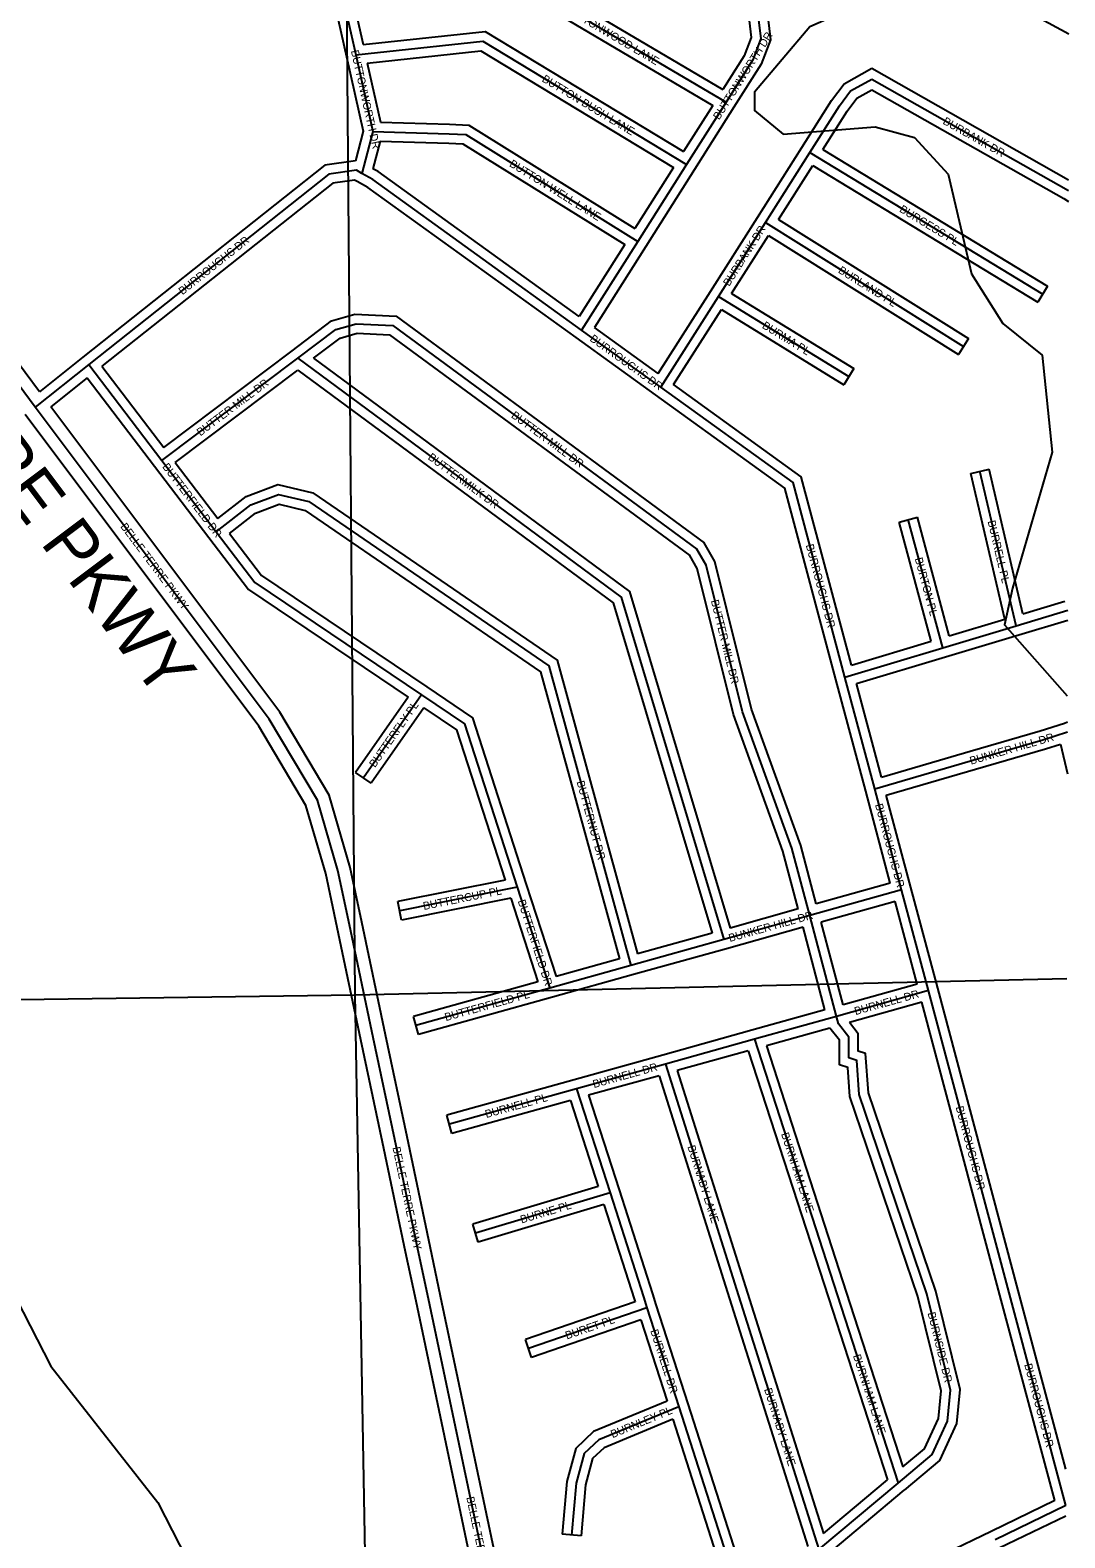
# Model space of a CAD drawing. Extents: x 457167 to 656239, y 1787309 to 1969297.
# Drawn here: x 573475 to 576766, y 1906785 to 1911582 of the extents above; entities that cross this region are included whole.
import ezdxf

# ---------------------------------------------------------------- set-up
doc = ezdxf.new("R2010")
doc.units = 0
for name, color, linetype in [('Level 1', 7, 'Continuous'), ('Level 22', 7, 'Continuous'), ('Level 23', 7, 'Continuous'), ('Level 28', 7, 'Continuous'), ('Level 31', 7, 'Continuous'), ('Level 32', 7, 'Continuous'), ('Level 34', 7, 'Continuous'), ('Level 7', 7, 'Continuous')]:
    doc.layers.add(name, color=color, linetype=linetype)

msp = doc.modelspace()

# ---------------------------------------------------------------- linework, layer by layer
at = {"layer": 'Level 1'}
for p, q in [((574508.155, 1908512.577), (574465.56, 1913625.261)), ((574508.155, 1908512.577), (576773.088, 1908564.556)), ((569209.114, 1908436.293), (574508.155, 1908512.577)), ((574605.324, 1903226.441), (574508.155, 1908512.577))]:
    msp.add_line(p, q, dxfattribs=at)
at = {"layer": 'Level 22'}
for p, q in [((573490.678, 1910382.465), (572685.119, 1911456.291)), ((574566.005, 1908377.134), (574490.505, 1908735.125)), ((574634.585, 1908052.25), (574566.005, 1908377.134)), ((574708.201, 1907703.355), (574634.585, 1908052.25)), ((574741.549, 1907545.461), (574708.201, 1907703.355)), ((575070.95, 1905983.62), (574741.549, 1907545.461))]:
    msp.add_line(p, q, dxfattribs=at)
msp.add_lwpolyline([(574490.505, 1908735.125), (574454.014, 1908907.936), (574388.708, 1909131.357), (574235.434, 1909389.518), (573490.678, 1910382.465)], dxfattribs=at)
at = {"layer": 'Level 23'}
for p, q in [((573504.03, 1910431.324), (572735.449, 1911455.859)), ((574526.865, 1908368.879), (574451.365, 1908726.871)), ((574605.144, 1908385.388), (574529.645, 1908743.379)), ((574595.448, 1908043.987), (574526.866, 1908368.871)), ((574673.725, 1908060.511), (574605.143, 1908385.396)), ((574669.062, 1907695.096), (574595.447, 1908043.991)), ((574747.341, 1907711.613), (574673.725, 1908060.508)), ((574702.411, 1907537.194), (574669.064, 1907695.088)), ((574780.687, 1907553.726), (574747.34, 1907711.621)), ((575104.96, 1906016.193), (574780.689, 1907553.715)), ((575031.81, 1905975.365), (574702.41, 1907537.206))]:
    msp.add_line(p, q, dxfattribs=at)
for points in [[(574529.642, 1908743.39), (574492.835, 1908917.694), (574425.685, 1909147.431), (574268.728, 1909411.795), (573540.047, 1910383.308)], [(574451.367, 1908726.861), (574415.191, 1908898.179), (574351.732, 1909115.283), (574202.139, 1909367.242), (573458.679, 1910358.462)]]:
    msp.add_lwpolyline(points, dxfattribs=at)
at = {"layer": 'Level 31'}
for p, q in [((574461.171, 1911722.884), (574510.587, 1911503.135)), ((574510.587, 1911503.135), (574564.721, 1911259.737)), ((575688.499, 1911352.555), (575563.155, 1911154.278)), ((574564.721, 1911259.737), (574530.099, 1911125.993)), ((575813.853, 1910969.73), (575955.14, 1911192.337)), ((575955.14, 1911192.337), (576696.021, 1910741.641)), ((575563.155, 1911154.278), (575408.15, 1910909.52)), ((575664.272, 1910734.414), (575813.853, 1910969.73)), ((575813.853, 1910969.73), (576444.564, 1910575.27)), ((575408.15, 1910909.52), (575229.223, 1910627.722)), ((575481.2, 1910446.079), (575664.272, 1910734.414)), ((575664.272, 1910734.414), (576079.148, 1910479.328)), ((575481.2, 1910446.079), (575229.223, 1910627.722)), ((573893.972, 1910212.473), (574326.015, 1910537.705)), ((573661.347, 1910517.723), (573490.678, 1910382.465)), ((573661.347, 1910517.723), (573893.972, 1910212.473)), ((573893.972, 1910212.473), (574066.7, 1909985.903)), ((576611.118, 1909686.896), (576496.156, 1910178.424)), ((576377.978, 1909616.85), (576268.241, 1910024.366)), ((576611.118, 1909686.896), (576775.555, 1909736.362)), ((576377.978, 1909616.85), (576611.118, 1909686.896)), ((576066.912, 1909523.336), (576377.978, 1909616.85)), ((576161.82, 1909167.853), (576066.912, 1909523.336)), ((574719.387, 1909467.363), (574534.764, 1909202.673)), ((576474.155, 1909259.181), (576696.162, 1909324.161)), ((576696.162, 1909324.161), (576774.725, 1909348.72)), ((576161.82, 1909167.853), (576474.155, 1909259.181)), ((576247.268, 1908846.571), (576161.82, 1909167.853)), ((575024.462, 1908854.682), (574650.489, 1908779.501)), ((575024.462, 1908854.682), (575128.02, 1908533.722)), ((576247.268, 1908846.571), (575954.655, 1908764.656)), ((576333.036, 1908525.654), (576247.268, 1908846.571)), ((575954.655, 1908764.656), (575681.761, 1908688.155)), ((576039.785, 1908443.739), (575954.655, 1908764.656)), ((575681.761, 1908688.155), (575385.966, 1908605.525)), ((575385.966, 1908605.525), (575128.02, 1908533.722)), ((575128.02, 1908533.722), (574701.817, 1908415.018)), ((576333.036, 1908525.654), (576039.785, 1908443.739)), ((576589.081, 1907564.359), (576333.036, 1908525.654)), ((576039.785, 1908443.739), (575778.976, 1908370.848)), ((575778.976, 1908370.848), (575495.584, 1908291.826)), ((575778.976, 1908370.848), (576042.639, 1907557.535)), ((575495.584, 1908291.826), (575213.144, 1908213.167)), ((575495.584, 1908291.826), (575728.572, 1907554.579)), ((575213.144, 1908213.167), (574808.567, 1908100.596)), ((575213.144, 1908213.167), (575319.545, 1907882.384)), ((575319.545, 1907882.384), (574891.725, 1907753.861)), ((575319.545, 1907882.384), (575425.63, 1907551.601)), ((575425.63, 1907551.601), (575436.998, 1907516.666)), ((575728.572, 1907554.579), (575983.352, 1906747.104)), ((576042.639, 1907557.535), (576236.524, 1906958.925)), ((576403.092, 1907254.207), (576327.462, 1907560.557)), ((576769.456, 1906887.233), (576589.081, 1907564.359)), ((575436.998, 1907516.666), (575060.35, 1907386.941)), ((575436.998, 1907516.666), (575538.351, 1907201.895)), ((575538.351, 1907201.895), (575747.69, 1906549.792)), ((575983.352, 1906747.104), (576236.524, 1906958.925)), ((576769.456, 1906887.233), (576544.798, 1906778.259))]:
    msp.add_line(p, q, dxfattribs=at)
for points in [[(574705.365, 1911764.892), (574925.71, 1911802.956), (575688.499, 1911352.555)], [(575790.176, 1911630.885), (575799.546, 1911554.863), (575773.336, 1911486.919), (575688.499, 1911352.555)], [(574510.587, 1911503.135), (574915.295, 1911546.973), (575563.155, 1911154.278)], [(575955.14, 1911192.337), (576049.225, 1911341.228), (576084.29, 1911388.426), (576152.072, 1911426.098)], [(576152.072, 1911426.098), (576778.415, 1911071.653), (576778.453, 1911071.63)], [(574564.721, 1911259.737), (574807.855, 1911252.294), (574860.611, 1911249.633), (575408.15, 1910909.52)], [(574530.099, 1911125.993), (574512.639, 1911135.85), (574424.887, 1911123.679), (573661.347, 1910517.723)], [(575229.223, 1910627.722), (574565.337, 1911106.642), (574530.099, 1911125.993)], [(574326.015, 1910537.705), (574447.319, 1910629.438), (574511.564, 1910647.479), (574628.838, 1910642.13), (575595.777, 1909930.547)], [(574326.015, 1910537.705), (575355.464, 1909777.976), (575681.761, 1908688.155)], [(576066.912, 1909523.336), (575901.695, 1910142.979), (575481.2, 1910446.079)], [(574066.7, 1909985.903), (574176.867, 1910071.843), (574264.666, 1910104.376), (574361.562, 1910081.616), (575124.857, 1909558.84), (575385.966, 1908605.525)], [(574066.7, 1909985.903), (574189.67, 1909824.537), (574719.387, 1909467.363)], [(575954.655, 1908764.656), (575897.585, 1908978.966), (575740.55, 1909412.768), (575624.91, 1909879.937), (575595.777, 1909930.547)], [(574719.387, 1909467.363), (574856.182, 1909375.061), (575024.462, 1908854.682)], [(576327.462, 1907560.557), (576112.358, 1908194.851), (576104.327, 1908303.234), (576079.234, 1908311.652), (576079.377, 1908378.198), (576046.092, 1908420.089), (576039.785, 1908443.739)], [(576236.524, 1906958.925), (576344.163, 1907049.603), (576393.664, 1907156.044), (576403.092, 1907254.207)], [(575538.351, 1907201.895), (575283.82, 1907096.992), (575237.313, 1907052.73), (575211.358, 1906958.239), (575197.33, 1906793.54)]]:
    msp.add_lwpolyline(points, dxfattribs=at)
at = {"layer": 'Level 32'}
for p, q in [((574431.902, 1911716.302), (574481.319, 1911496.552)), ((574497.366, 1911698.668), (574533.981, 1911535.844)), ((576649.511, 1911639.646), (576779.519, 1911570.011)), ((574481.303, 1911496.621), (574533.87, 1911260.268)), ((574547.153, 1911476.918), (574588.945, 1911289.011)), ((576152.205, 1911460.493), (576778.526, 1911106.061)), ((575646.616, 1911342.445), (575553.53, 1911195.194)), ((575713.858, 1911336.524), (575588.515, 1911138.247)), ((574533.87, 1911260.269), (574509.385, 1911165.686)), ((574587.76, 1911229.016), (574564.99, 1911141.059)), ((575788.524, 1910985.806), (575929.811, 1911208.413)), ((575996.804, 1911202.108), (576711.614, 1910767.272)), ((575521.441, 1911144.481), (575398.717, 1910950.696)), ((575855.367, 1910979.151), (575964.696, 1911151.408)), ((575964.696, 1911151.407), (576680.43, 1910716.01)), ((575588.501, 1911138.226), (575433.495, 1910893.468)), ((575638.954, 1910750.507), (575788.535, 1910985.823)), ((575855.367, 1910979.151), (576460.472, 1910600.705)), ((575705.928, 1910744.02), (575823.196, 1910928.501)), ((575823.196, 1910928.501), (576428.656, 1910549.834)), ((575366.582, 1910900.022), (575220.96, 1910670.676)), ((575433.477, 1910893.438), (575269.712, 1910635.518)), ((576711.614, 1910767.272), (576680.43, 1910716.01)), ((575472.93, 1910489.022), (575638.945, 1910750.494)), ((575705.928, 1910744.019), (576094.861, 1910504.884)), ((575521.689, 1910453.876), (575673.75, 1910693.369)), ((575673.75, 1910693.369), (576063.435, 1910453.771)), ((575472.93, 1910489.022), (575269.712, 1910635.518)), ((575463.656, 1910421.742), (575211.68, 1910603.386)), ((576460.472, 1910600.705), (576428.656, 1910549.834)), ((573642.714, 1910541.236), (573504.03, 1910431.325)), ((573899.757, 1910254.376), (574307.973, 1910561.672)), ((573656.02, 1910475.219), (573540.046, 1910383.308)), ((573656.02, 1910475.22), (573870.11, 1910194.288)), ((573703.04, 1910512.51), (573899.757, 1910254.377)), ((573936.13, 1910206.656), (574326.194, 1910500.287)), ((576094.861, 1910504.884), (576063.435, 1910453.771)), ((573870.114, 1910194.284), (574042.842, 1909967.714)), ((573936.13, 1910206.656), (574072.167, 1910028.216)), ((576466.945, 1910171.591), (576525.37, 1910185.256)), ((576633.059, 1909724.823), (576525.37, 1910185.256)), ((576575.485, 1909707.514), (576466.945, 1910171.591)), ((576239.274, 1910016.565), (576297.21, 1910032.167)), ((576341.433, 1909637.189), (576239.274, 1910016.565)), ((576398.918, 1909654.466), (576297.21, 1910032.167)), ((576633.058, 1909724.823), (576766.468, 1909764.956)), ((576398.918, 1909654.466), (576575.485, 1909707.515)), ((576619.761, 1909658.166), (576775.528, 1909705.024)), ((576386.611, 1909588.117), (576619.751, 1909658.163)), ((576087.925, 1909560.98), (576341.432, 1909637.19)), ((576103.4, 1909502.976), (576386.615, 1909588.118)), ((576132.835, 1909160.114), (576037.927, 1909515.598)), ((576182.882, 1909205.267), (576103.4, 1909502.978)), ((574677.345, 1909459.527), (574510.158, 1909219.836)), ((574727.095, 1909425.971), (574559.37, 1909185.51)), ((576687.473, 1909352.876), (576764.875, 1909377.072)), ((576764.875, 1909377.072), (576774.835, 1909380.887)), ((576465.729, 1909287.974), (576687.472, 1909352.876)), ((576182.882, 1909205.268), (576465.736, 1909287.976)), ((576482.584, 1909230.388), (576704.853, 1909295.445)), ((576704.852, 1909295.445), (576752.742, 1909310.415)), ((576752.743, 1909310.415), (576774.482, 1909215.836)), ((576198.338, 1909147.273), (576482.576, 1909230.386)), ((574559.37, 1909185.51), (574510.158, 1909219.836)), ((576210.665, 1908867.477), (576132.828, 1909160.141)), ((576276.26, 1908854.281), (576198.338, 1909147.273)), ((574985.566, 1908877.462), (574644.577, 1908808.913)), ((575053.013, 1908863.894), (575147.726, 1908570.348)), ((576210.664, 1908867.478), (575975.828, 1908801.736)), ((576362.02, 1908533.399), (576276.251, 1908854.316)), ((574656.402, 1908750.089), (574644.577, 1908808.913)), ((575004.131, 1908819.994), (574656.402, 1908750.089)), ((575004.132, 1908819.994), (575089.877, 1908554.241)), ((576226.124, 1908809.496), (575991.242, 1908743.743)), ((576296.395, 1908546.566), (576226.124, 1908809.496)), ((575918.046, 1908785.55), (575702.048, 1908724.998)), ((575644.256, 1908708.826), (575406.936, 1908642.531)), ((575933.459, 1908727.556), (575689.86, 1908659.268)), ((576003.198, 1908464.662), (575933.46, 1908727.556)), ((576060.99, 1908480.811), (575991.241, 1908743.744)), ((575689.834, 1908659.261), (575394.039, 1908576.63)), ((575349.14, 1908626.413), (575147.726, 1908570.349)), ((575089.876, 1908554.241), (574693.769, 1908443.919)), ((575394.012, 1908576.622), (575136.065, 1908504.821)), ((576296.395, 1908546.566), (576060.99, 1908480.81)), ((576618.071, 1907572.081), (576362.026, 1908533.375)), ((575136.07, 1908504.821), (574709.867, 1908386.117)), ((576003.198, 1908464.662), (575770.902, 1908399.741)), ((576311.862, 1908488.589), (576081.18, 1908424.152)), ((576560.091, 1907556.636), (576311.862, 1908488.588)), ((574709.867, 1908386.117), (574693.769, 1908443.919)), ((575770.92, 1908399.746), (575487.526, 1908320.724)), ((576018.621, 1908406.673), (575817.154, 1908350.366)), ((575487.535, 1908320.726), (575205.096, 1908242.067)), ((575759.313, 1908334.218), (575533.545, 1908271.265)), ((575759.314, 1908334.218), (576014.101, 1907548.283)), ((575817.154, 1908350.366), (576071.178, 1907566.786)), ((575533.545, 1908271.265), (575757.178, 1907563.619)), ((575205.103, 1908242.069), (574800.525, 1908129.499)), ((575475.712, 1908255.148), (575251.262, 1908192.64)), ((575475.712, 1908255.148), (575699.966, 1907545.539)), ((575193.414, 1908176.536), (574816.609, 1908071.693)), ((575193.414, 1908176.535), (575281.62, 1907902.315)), ((575251.262, 1908192.64), (575348.105, 1907891.57)), ((574816.609, 1908071.693), (574800.525, 1908129.499)), ((575281.62, 1907902.315), (574883.094, 1907782.593)), ((575348.114, 1907891.545), (575454.159, 1907560.883)), ((575299.973, 1907845.177), (574900.357, 1907725.13)), ((575299.972, 1907845.177), (575397.063, 1907542.439)), ((574900.357, 1907725.13), (574883.094, 1907782.593)), ((575454.159, 1907560.883), (575465.526, 1907525.949)), ((575699.962, 1907545.551), (575948.703, 1906757.219)), ((575757.182, 1907563.606), (575998.476, 1906798.873)), ((576014.099, 1907548.291), (576201.745, 1906968.941)), ((576071.18, 1907566.779), (576251.318, 1907010.614)), ((576372.741, 1907251.982), (576298.642, 1907552.128)), ((576433.445, 1907256.431), (576356.283, 1907568.985)), ((576734.097, 1906903.424), (576560.091, 1907556.636)), ((576769.747, 1907002.723), (576618.071, 1907572.081)), ((575399.345, 1907535.427), (575050.58, 1907415.306)), ((575397.102, 1907542.318), (575399.345, 1907535.427)), ((575465.555, 1907525.861), (575566.909, 1907211.09)), ((575417.825, 1907478.331), (575070.12, 1907358.576)), ((575417.825, 1907478.331), (575501.303, 1907219.073)), ((575070.12, 1907358.576), (575050.58, 1907415.306)), ((575566.917, 1907211.065), (575762.625, 1906601.422)), ((575519.725, 1907161.768), (575719.126, 1906540.621)), ((575998.476, 1906798.873), (576201.745, 1906968.941)), ((576002.604, 1906724.095), (576255.775, 1906935.916)), ((576734.097, 1906903.424), (576531.705, 1906805.251)), ((576769.428, 1906853.875), (576557.892, 1906751.266)), ((575227.222, 1906790.994), (575167.438, 1906796.086))]:
    msp.add_line(p, q, dxfattribs=at)
for points in [[(574728.836, 1911799.391), (574931.469, 1911834.396), (575678.679, 1911393.193)], [(574710.47, 1911735.329), (574919.951, 1911771.516), (575646.616, 1911342.445)], [(575818.104, 1911649.545), (575830.241, 1911551.076), (575800.27, 1911473.383), (575713.866, 1911336.538)], [(574533.982, 1911535.844), (574922.161, 1911577.893), (575553.53, 1911195.194)], [(575762.25, 1911612.223), (575768.851, 1911558.651), (575746.402, 1911500.455), (575678.679, 1911393.193)], [(574547.153, 1911476.918), (574908.43, 1911516.053), (575521.44, 1911144.481)], [(575929.779, 1911208.363), (576024.47, 1911358.211), (576064.065, 1911411.507), (576152.205, 1911460.494)], [(575996.803, 1911202.107), (576073.982, 1911324.246), (576104.515, 1911365.343), (576151.94, 1911391.701)], [(576151.94, 1911391.701), (576763.143, 1911045.825), (576778.377, 1911036.421)], [(574588.945, 1911289.011), (574809.07, 1911282.271), (574869.86, 1911279.206), (575398.716, 1910950.696)], [(574587.759, 1911229.016), (574806.64, 1911222.316), (574851.362, 1911220.061), (575366.582, 1910900.022)], [(574509.385, 1911165.686), (574412.654, 1911152.271), (573642.697, 1910541.223)], [(574515.35, 1911099.867), (574506.719, 1911104.741), (574437.121, 1911095.088), (573703.04, 1910512.51)], [(575211.671, 1910603.391), (574549.28, 1911081.233), (574515.35, 1911099.867)], [(575220.96, 1910670.676), (574581.394, 1911132.051), (574564.99, 1911141.059)], [(574307.92, 1910561.633), (574433.747, 1910656.789), (574508.105, 1910677.669), (574639.293, 1910671.685), (575618.635, 1909950.975)], [(574376.141, 1910537.997), (574460.89, 1910602.088), (574515.024, 1910617.289), (574618.383, 1910612.575), (575572.921, 1909910.118)], [(574376.142, 1910537.997), (575381.332, 1909796.171), (575702.047, 1908724.998)], [(574326.193, 1910500.287), (575329.595, 1909759.781), (575644.256, 1908708.826)], [(576087.925, 1909560.98), (575927.925, 1910161.055), (575521.688, 1910453.876)], [(576037.924, 1909515.608), (575875.466, 1910124.903), (575463.657, 1910421.741)], [(574072.167, 1910028.216), (574162.082, 1910098.359), (574262.722, 1910135.651), (574373.884, 1910109.539), (575150.885, 1909577.376), (575406.937, 1908642.531)], [(574108.542, 1909980.493), (574191.653, 1910045.328), (574266.61, 1910073.103), (574349.24, 1910053.694), (575098.829, 1909540.304), (575349.14, 1908626.413)], [(574042.838, 1909967.719), (574168.803, 1909802.424), (574677.345, 1909459.527)], [(574108.541, 1909980.493), (574210.538, 1909846.651), (574736.159, 1909492.237)], [(575975.828, 1908801.736), (575926.24, 1908987.949), (575769.293, 1909421.502), (575653.016, 1909891.245), (575618.635, 1909950.975)], [(575918.046, 1908785.55), (575868.932, 1908969.983), (575711.805, 1909404.035), (575596.802, 1909868.63), (575572.921, 1909910.118)], [(574736.167, 1909492.232), (574881.542, 1909394.141), (575053.007, 1908863.913)], [(574727.095, 1909425.971), (574830.821, 1909355.981), (574985.566, 1908877.463)], [(576356.284, 1907568.985), (576141.994, 1908200.872), (576132.772, 1908325.335), (576109.28, 1908333.216), (576109.4, 1908388.636), (576081.18, 1908424.152)], [(576298.641, 1907552.128), (576082.721, 1908188.828), (576075.882, 1908281.133), (576049.187, 1908290.089), (576049.355, 1908367.759), (576018.715, 1908406.321), (576018.621, 1908406.672)], [(575501.303, 1907219.074), (575267.201, 1907122.592), (575210.593, 1907068.715), (575181.7, 1906963.53), (575167.438, 1906796.086)], [(576251.318, 1907010.614), (576319.759, 1907068.271), (576364.292, 1907164.031), (576372.74, 1907251.983)], [(576255.853, 1906935.981), (576368.567, 1907030.935), (576423.035, 1907148.056), (576433.446, 1907256.431)], [(575519.725, 1907161.768), (575300.44, 1907071.393), (575264.034, 1907036.745), (575241.017, 1906952.949), (575227.222, 1906790.994)], [(576531.745, 1906805.271), (576095.686, 1906594.556), (575995.722, 1906400.816)]]:
    msp.add_lwpolyline(points, dxfattribs=at)
at = {"layer": 'Level 7'}
for points in [[(576780.451, 1912005.73), (576640.126, 1911973.185), (576439.505, 1911807.118), (575955.308, 1911591.906), (575779.587, 1911384.05), (575779.398, 1911325.698), (575870.831, 1911250.377), (576162.706, 1911274.472), (576287.65, 1911240.703), (576395.633, 1911123.661), (576469.639, 1910806.625), (576569.153, 1910647.932), (576693.906, 1910547.471), (576726.241, 1910238.934), (576599.825, 1909805.832), (576574.415, 1909689.219), (576773.772, 1909463.486)], [(573341.919, 1907715.53), (573540.748, 1907331.403), (573881.14, 1906896.837), (574295.369, 1906086.863), (574336.591, 1905945.021), (574502.21, 1905594.334), (574510.32, 1905527.642), (574535.261, 1905510.872), (574535.132, 1905460.851), (574576.643, 1905410.701), (574782.995, 1904776.488), (574797.615, 1904126.182), (574746.448, 1903776.223)]]:
    msp.add_lwpolyline(points, dxfattribs=at)

# ---------------------------------------------------------------- texts
at = {"layer": 'Level 28'}
msp.add_text('BELLE TERRE PKWY', height=160, rotation=306.875711, dxfattribs=at).set_placement((572598.469, 1911158.419))
at = {"layer": 'Level 34'}
for s, height, rotation, p in [('BUTTONWOOD LANE', 25, 329.438986, (575172.196, 1911642.899)), ('BUTTONWORTH DR', 25, 57.730783, (575666.574, 1911294.42)), ('BUTTONWORTH DR', 24.99916, 282.538136, (574494.994, 1911515.686)), ('BUTTON BUSH LANE', 25, 328.777547, (575100.634, 1911420.016)), ('BURBANK DR', 25, 330.494053, (576376.031, 1911284.999)), ('BUTTON WELL LANE', 25, 328.152219, (574996.955, 1911150.227)), ('BURGESS PL', 25, 328.686256, (576237.955, 1911005.664)), ('BURBANK DR', 25, 57.556728, (575698.415, 1910764.828)), ('BURROUGHS DR', 25, 38.435144, (573959.11, 1910738.076)), ('BURLAND PL', 25, 327.976639, (576043.27, 1910811.506)), ('BURMA PL', 25, 328.414214, (575801.173, 1910635.568)), ('BURROUGHS DR', 25, 324.212475, (575252.858, 1910595.277)), ('BUTTER MILL DR', 25, 36.970636, (574016.354, 1910288.956)), ('BUTTER MILL DR', 25, 323.64955, (575002.922, 1910351.318)), ('BUTTERMILK DR', 25, 323.572239, (574737.905, 1910218.198)), ('BUTTERFIELD DR', 25, 307.319914, (573893.633, 1910192.301)), ('BELLE TERRE PKWY', 25, 306.870986, (573760.36, 1910002.08)), ('BURRELL PL', 25, 283.163336, (576520.594, 1910019.058)), ('BURROUGHS DR', 25, 284.928872, (575942.041, 1909943.147)), ('BURTON PL', 25, 285.070444, (576288.683, 1909900.385)), ('BUTTER MILL DR', 25, 283.902414, (575640.175, 1909766.255)), ('BUTTERFLY PL', 25, 55.103072, (574571.649, 1909233.707)), ('BUNKER HILL DR', 25, 16.313489, (576468.06, 1909244.375)), ('BUTTERNUT DR', 25, 285.316761, (575212.905, 1909190.061)), ('BURROUGHS DR', 25, 284.892928, (576162.35, 1909117.229)), ('BUTTERCUP PL', 25, 11.366039, (574727.387, 1908782.211)), ('BUTTERFIELD DR', 25, 287.881667, (575025.468, 1908810.862)), ('BUNKER HILL DR', 25, 15.659072, (575700.577, 1908680.451)), ('BUTTERFIELD PL', 25, 15.5626, (574797.21, 1908428.612)), ('BURNELL DR', 25, 15.605978, (576100.59, 1908447.746)), ('BURNELL DR', 25, 15.561564, (575268.513, 1908215.613)), ('BURNELL PL', 25, 15.548081, (574925.907, 1908120.271)), ('BURROUGHS DR', 25, 284.914025, (576418.825, 1908155.008)), ('BURNHAM LANE', 25, 287.961175, (575863.37, 1908069.995)), ('BELLE TERRE PKWY', 25, 281.9137, (574627.27, 1908026.382)), ('BURNABY LANE', 25, 287.537139, (575565.423, 1908029.353)), ('BURNE PL', 25, 16.719994, (575038.195, 1907784.811)), ('BURNSIDE DR', 25, 283.867089, (576329.59, 1907499.79)), ('BURET PL', 25, 19.003989, (575182.166, 1907415.677)), ('BURNELL DR', 25, 287.847431, (575447.396, 1907443.591)), ('BURNHAM LANE', 25, 287.94605, (576092.17, 1907364.046)), ('BURROUGHS DR', 25, 284.915572, (576637.031, 1907335.796)), ('BURNABY LANE', 25, 287.511172, (575809.355, 1907257.014)), ('BURNLEY PL', 25, 22.397589, (575327.615, 1907101.524)), ('BELLE TERRE PKWY', 24.99916, 281.908747, (574862.14, 1906913.118))]:
    msp.add_text(s, height=height, rotation=rotation, dxfattribs=at).set_placement(p)

doc.saveas('drawing.dxf')
